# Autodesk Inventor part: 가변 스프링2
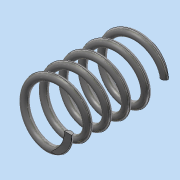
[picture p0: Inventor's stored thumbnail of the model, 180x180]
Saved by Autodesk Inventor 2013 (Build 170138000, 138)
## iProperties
Created: 2015-02
Part Number: 가변 스프링2
Material: 강철, 탄소
Document SubType Name: Modeling
Designer: dgall
Density: 7.87 g/cm^3
Mass: 18.9085 g
Surface Area: 32.5524 cm^2
Volume: 2.40261 cm^3
Author: dgall
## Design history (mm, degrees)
sketch "스케치1"
  geometry: L1 (11, 0)-(0, 0); L2 (0, 0)-(0, 40.095); L3 (0, 40.095)-(11, 40.095); C1 r 1.5 at (11, 0)
  constraints: 6 end point, 2 horizontal, 1 centre point, 1 coincident, 1 vertical, 1 vertical alignment
  dimensions: "d0" = 3 diameter of C1; "d2" = 40.0955 distance of L1.end L2.end (derived); "d4" = 22 diameter of C1.centre L2
feature "코일1" pitch "d5" = 10; turns "d7" = 5; dims "d6" = 40.0955 (= d2), "d8" = 0, angle "d9" = 90 deg, angle "d10" = 90 deg, "d11" = 0, "d12" = 0
sketch "스케치2"
  geometry: L1 (23.568, 52.729)-(-15.257, 52.729); L2 (-15.257, 52.729)-(-15.257, 40.095); L3 (-15.257, 40.095)-(23.568, 40.095); L4 (23.568, 40.095)-(23.568, 52.729); L5 (21.719, -8.918)-(-15.91, -8.918); L6 (-15.91, -8.918)-(-15.91, 0); L7 (-15.91, 0)-(21.719, 0); L8 (21.719, 0)-(21.719, -8.918); 5 further points
  constraints: 16 end point, 2 horizontal, 2 horizontal alignment, 2 point on line, 1 vertical alignment
extrude "돌출1" cut sketch "스케치2" stored distance "d13" = 10; taper "d14" = 0 deg
node "솔리드1"
node "투영된 루프1"
